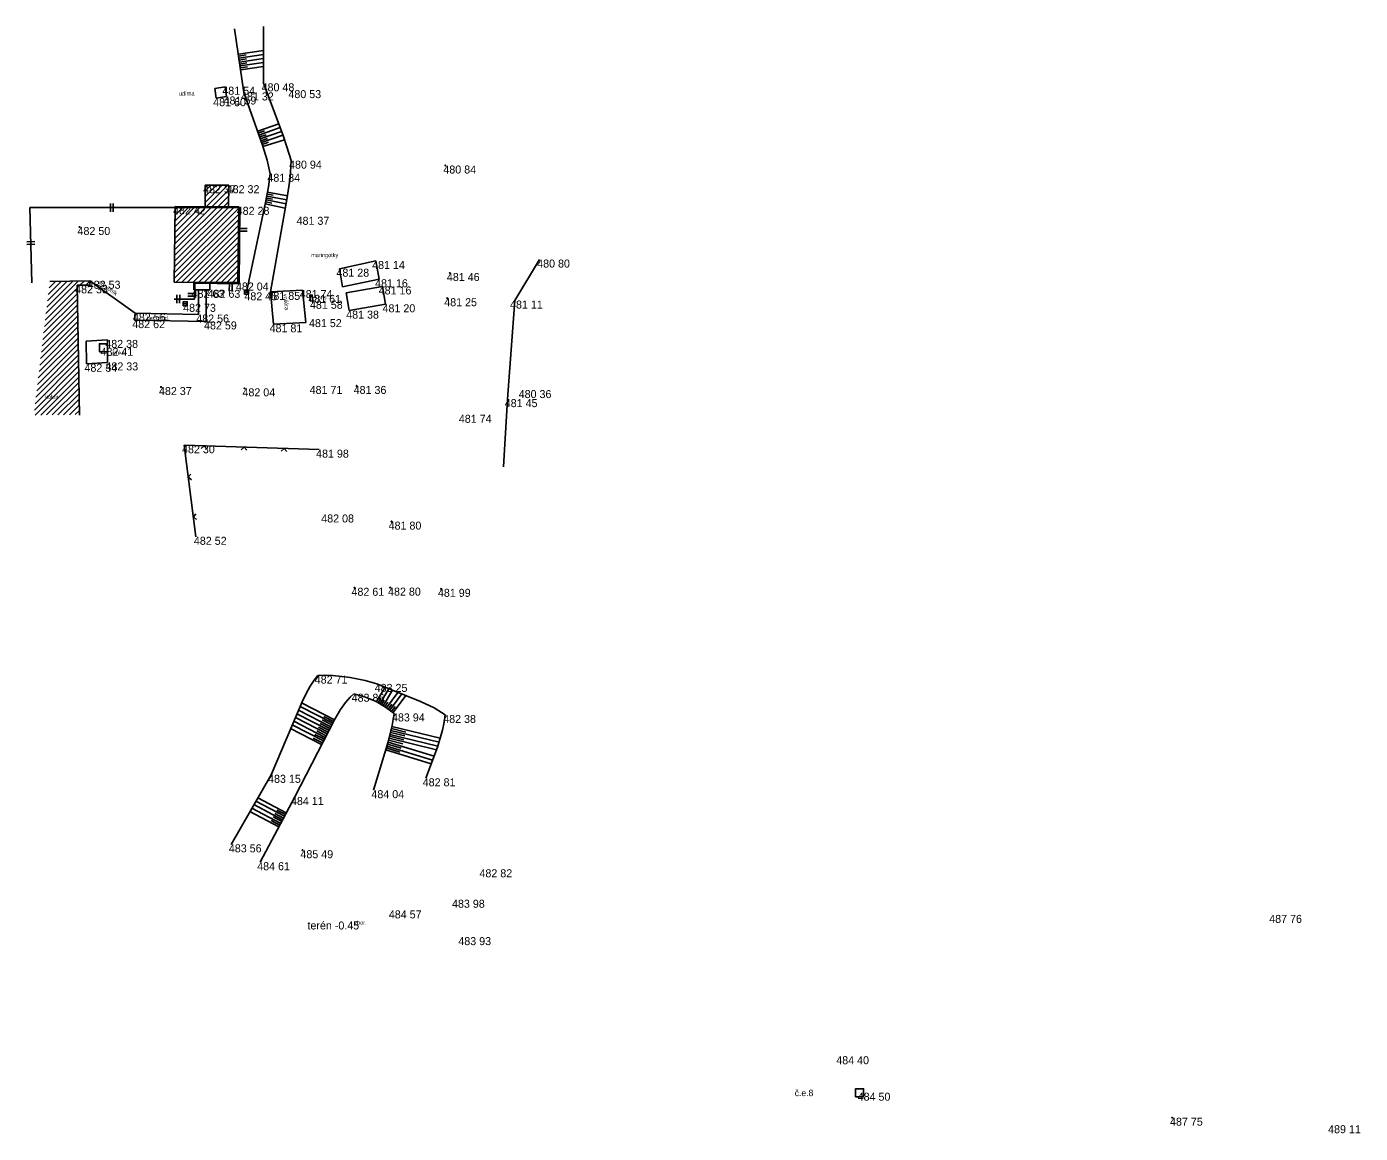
# Model space of a CAD drawing. Extents: x -553666 to -553461, y -1076543 to -1076230.
# Drawn here: x -553665.9 to -553499.2, y -1076368.4 to -1076230.1 of the extents above; entities that cross this region are included whole.
import ezdxf

# ---------------------------------------------------------------- set-up
doc = ezdxf.new("R2010")
doc.units = 0
for name, color, linetype in [('1', 7, 'Continuous'), ('12', 7, 'Continuous'), ('14', 7, 'Continuous'), ('17', 7, 'Continuous'), ('18', 7, 'Continuous'), ('26', 7, 'Continuous'), ('27', 7, 'Continuous'), ('32', 7, 'Continuous'), ('40', 7, 'Continuous'), ('50', 7, 'Continuous'), ('52', 7, 'Continuous'), ('54', 7, 'Continuous'), ('6', 7, 'Continuous'), ('62', 7, 'Continuous')]:
    doc.layers.add(name, color=color, linetype=linetype)

# ---------------------------------------------------------------- blocks, each defined once
blk = doc.blocks.new('POINT_DISPLAY')
blk.add_line((0, 0), (0, 0))
blk = doc.blocks.new('T')
at = {"layer": '6'}
blk.add_circle((0, 0), 0.05, dxfattribs=at)
blk = doc.blocks.new('VP')
at = {"layer": '40'}
blk.add_line((-0.25, 0), (0.25, 0), dxfattribs=at)
blk.add_lwpolyline([(-0.25, -0.25), (0.25, -0.25), (0.25, 0.25), (-0.25, 0.25)], close=True, dxfattribs=at)
blk = doc.blocks.new('SA')
at = {"layer": '50'}
blk.add_lwpolyline([(-0.5, -0.5), (0.5, -0.5), (0.5, 0.5), (-0.5, 0.5)], close=True, dxfattribs=at)
blk = doc.blocks.new('ROV')
at = {"layer": '62'}
for p, q in [((-0.348, -0.51), (-0.348, 0.51)), ((0, -0.51), (0, 0.51))]:
    blk.add_line(p, q, dxfattribs=at)

msp = doc.modelspace()

# ---------------------------------------------------------------- linework, layer by layer
at = {"layer": '12'}
for p, q in [((-553644.72, -1076293.84), (-553646.2, -1076282.4)), ((-553646.2, -1076282.4), (-553629.33, -1076282.95)), ((-553643.7, -1076282.48), (-553644.07, -1076282.82)), ((-553643.7, -1076282.48), (-553643.36, -1076282.85)), ((-553638.7, -1076282.64), (-553639.07, -1076282.99)), ((-553638.7, -1076282.64), (-553638.36, -1076283.01)), ((-553633.71, -1076282.81), (-553634.07, -1076283.15)), ((-553633.71, -1076282.81), (-553633.36, -1076283.17)), ((-553645.68, -1076286.4), (-553645.38, -1076286.01)), ((-553645.68, -1076286.4), (-553645.29, -1076286.71)), ((-553645.04, -1076291.36), (-553644.73, -1076290.96)), ((-553645.04, -1076291.36), (-553644.64, -1076291.67))]:
    msp.add_line(p, q, dxfattribs=at)
at = {"layer": '14'}
for p, q in [((-553641.07, -1076237.61), (-553642.37, -1076237.82)), ((-553642.37, -1076237.82), (-553642.19, -1076239.04)), ((-553641.07, -1076237.61), (-553640.89, -1076238.83)), ((-553640.89, -1076238.83), (-553642.19, -1076239.04)), ((-553643.59, -1076252.58), (-553643.57, -1076249.92)), ((-553640.62, -1076249.91), (-553643.57, -1076249.92)), ((-553640.64, -1076252.6), (-553640.62, -1076249.91)), ((-553647.33, -1076252.56), (-553647.44, -1076262.02)), ((-553647.33, -1076252.56), (-553639.37, -1076252.61)), ((-553639.37, -1076252.61), (-553639.48, -1076262.07)), ((-553662.98, -1076261.94), (-553657.98, -1076261.85)), ((-553657.97, -1076262.39), (-553659.56, -1076262.42)), ((-553659.56, -1076262.42), (-553659.27, -1076278.63)), ((-553657.97, -1076262.39), (-553657.98, -1076261.85)), ((-553647.44, -1076262.02), (-553639.48, -1076262.07))]:
    msp.add_line(p, q, dxfattribs=at)
at = {"layer": '17'}
for p, q in [((-553644.41, -1076262.98), (-553644.41, -1076266.07)), ((-553643.44, -1076262.98), (-553643.44, -1076266.93)), ((-553652.33, -1076265.91), (-553652.41, -1076266.77)), ((-553652.33, -1076265.91), (-553644.41, -1076266.07)), ((-553652.41, -1076266.77), (-553643.44, -1076266.93))]:
    msp.add_line(p, q, dxfattribs=at)
at = {"layer": '18'}
for p, q in [((-553626.8, -1076260.34), (-553622.24, -1076259.38)), ((-553622.24, -1076259.38), (-553621.85, -1076261.66)), ((-553626.8, -1076260.34), (-553626.41, -1076262.62)), ((-553652.33, -1076265.91), (-553657.98, -1076261.85)), ((-553644.99, -1076262.04), (-553645, -1076262.98)), ((-553645, -1076262.98), (-553643, -1076262.98)), ((-553642.99, -1076262.05), (-553643, -1076262.98)), ((-553635.42, -1076263.24), (-553631.39, -1076263.01)), ((-553631.39, -1076263.01), (-553631.01, -1076267.06)), ((-553626.41, -1076262.62), (-553621.85, -1076261.66)), ((-553621.4, -1076262.56), (-553625.94, -1076263.35)), ((-553621.4, -1076262.56), (-553621.04, -1076264.79)), ((-553635.42, -1076263.24), (-553635.04, -1076267.29)), ((-553630.49, -1076263.64), (-553630.19, -1076263.61)), ((-553630.49, -1076263.64), (-553630.41, -1076264.38)), ((-553630.11, -1076264.35), (-553630.41, -1076264.38)), ((-553630.19, -1076263.61), (-553630.11, -1076264.35)), ((-553625.94, -1076263.35), (-553625.58, -1076265.58)), ((-553621.04, -1076264.79), (-553625.58, -1076265.58)), ((-553635.04, -1076267.29), (-553631.01, -1076267.06)), ((-553655.79, -1076269.24), (-553658.42, -1076269.41)), ((-553658.42, -1076269.41), (-553658.4, -1076272.22)), ((-553655.79, -1076269.24), (-553655.77, -1076272.05)), ((-553655.77, -1076272.05), (-553658.4, -1076272.22))]:
    msp.add_line(p, q, dxfattribs=at)
at = {"layer": '26'}
for p, q in [((-553639.42, -1076233.53), (-553636.27, -1076233.07)), ((-553639.39, -1076233.78), (-553638.45, -1076233.64)), ((-553639.35, -1076234.02), (-553636.27, -1076233.57)), ((-553639.31, -1076234.27), (-553638.4, -1076234.14)), ((-553639.28, -1076234.52), (-553636.27, -1076234.08)), ((-553639.24, -1076234.77), (-553638.35, -1076234.64)), ((-553639.21, -1076235.01), (-553636.27, -1076234.58)), ((-553639.17, -1076235.26), (-553638.3, -1076235.13)), ((-553639.13, -1076235.51), (-553636.27, -1076235.09)), ((-553637.01, -1076243.17), (-553634.38, -1076242.25)), ((-553636.85, -1076243.65), (-553634.21, -1076242.72)), ((-553636.93, -1076243.41), (-553636.14, -1076243.13)), ((-553636.76, -1076243.88), (-553635.97, -1076243.6)), ((-553636.68, -1076244.12), (-553634.03, -1076243.19)), ((-553636.6, -1076244.35), (-553635.8, -1076244.07)), ((-553636.52, -1076244.59), (-553633.86, -1076243.66)), ((-553636.43, -1076244.82), (-553635.64, -1076244.54)), ((-553636.36, -1076245.06), (-553633.65, -1076244.24)), ((-553635.87, -1076251.26), (-553633.38, -1076251.75)), ((-553635.82, -1076251.02), (-553635.08, -1076251.16)), ((-553635.77, -1076250.77), (-553633.3, -1076251.25)), ((-553636.06, -1076252.24), (-553633.56, -1076252.78)), ((-553636.01, -1076252), (-553635.26, -1076252.14)), ((-553635.96, -1076251.75), (-553633.47, -1076252.24)), ((-553635.92, -1076251.51), (-553635.17, -1076251.65)), ((-553622.18, -1076314.44), (-553621.1, -1076312.63)), ((-553621.76, -1076314.7), (-553620.63, -1076312.82)), ((-553621.33, -1076314.95), (-553620.16, -1076313.01)), ((-553627.42, -1076316.69), (-553631.52, -1076314.58)), ((-553621.97, -1076314.57), (-553621.64, -1076314.01)), ((-553621.54, -1076314.82), (-553621.2, -1076314.25)), ((-553621.11, -1076315.08), (-553620.76, -1076314.49)), ((-553620.91, -1076315.22), (-553619.48, -1076313.28)), ((-553620.5, -1076315.52), (-553619, -1076313.47)), ((-553620.1, -1076315.81), (-553618.52, -1076313.66)), ((-553628.1, -1076318.02), (-553632.1, -1076315.96)), ((-553627.87, -1076317.57), (-553631.91, -1076315.5)), ((-553627.64, -1076317.13), (-553631.71, -1076315.04)), ((-553627.53, -1076316.91), (-553628.76, -1076316.28)), ((-553620.7, -1076315.37), (-553620.26, -1076314.77)), ((-553620.3, -1076315.67), (-553619.84, -1076315.04)), ((-553629.02, -1076319.8), (-553632.89, -1076317.81)), ((-553628.79, -1076319.35), (-553632.69, -1076317.35)), ((-553628.56, -1076318.91), (-553632.5, -1076316.89)), ((-553628.33, -1076318.47), (-553632.3, -1076316.43)), ((-553628.22, -1076318.24), (-553629.41, -1076317.63)), ((-553627.99, -1076317.8), (-553629.19, -1076317.18)), ((-553627.76, -1076317.35), (-553628.97, -1076316.73)), ((-553620.36, -1076318.04), (-553614.34, -1076319.5)), ((-553620.3, -1076317.8), (-553618.49, -1076318.24)), ((-553620.24, -1076317.56), (-553614.2, -1076319.02)), ((-553628.9, -1076319.58), (-553630.07, -1076318.98)), ((-553628.67, -1076319.13), (-553629.85, -1076318.53)), ((-553628.44, -1076318.69), (-553629.63, -1076318.08)), ((-553620.72, -1076319.5), (-553614.97, -1076321.26)), ((-553620.66, -1076319.26), (-553618.88, -1076319.69)), ((-553620.6, -1076319.01), (-553614.66, -1076320.45)), ((-553620.54, -1076318.77), (-553618.75, -1076319.2)), ((-553620.48, -1076318.53), (-553614.49, -1076319.98)), ((-553620.42, -1076318.28), (-553618.62, -1076318.72)), ((-553621.01, -1076320.45), (-553615.33, -1076322.2)), ((-553620.94, -1076320.22), (-553619.23, -1076320.74)), ((-553620.87, -1076319.98), (-553615.15, -1076321.73)), ((-553620.79, -1076319.74), (-553619.07, -1076320.27)), ((-553634.13, -1076329.65), (-553637.73, -1076327.74)), ((-553633.89, -1076329.21), (-553637.48, -1076327.3)), ((-553633.66, -1076328.76), (-553637.23, -1076326.87)), ((-553633.43, -1076328.32), (-553636.98, -1076326.44)), ((-553633.54, -1076328.54), (-553634.61, -1076327.98)), ((-553634.36, -1076330.09), (-553637.98, -1076328.17)), ((-553634.24, -1076329.87), (-553635.33, -1076329.29)), ((-553634.01, -1076329.43), (-553635.09, -1076328.85)), ((-553633.78, -1076328.99), (-553634.85, -1076328.42))]:
    msp.add_line(p, q, dxfattribs=at)
at = {"layer": '27'}
for p, q in [((-553638.72, -1076238.32), (-553639.89, -1076230.36)), ((-553636.28, -1076230.1), (-553636.27, -1076237.18)), ((-553601.82, -1076259.2), (-553604.89, -1076264.32)), ((-553604.89, -1076264.32), (-553605.78, -1076276.64)), ((-553605.78, -1076276.64), (-553606.31, -1076285.09)), ((-553640.34, -1076332.27), (-553635.34, -1076323.58)), ((-553636.7, -1076334.5), (-553632.38, -1076326.35))]:
    msp.add_line(p, q, dxfattribs=at)
for points in [[(-553636.27, -1076237.18), (-553633.84, -1076243.71), (-553633.35, -1076245.1), (-553632.83, -1076246.84)], [(-553638.72, -1076238.32), (-553636.41, -1076244.89), (-553635.84, -1076246.77), (-553635.44, -1076248.48)], [(-553632.83, -1076246.84), (-553632.96, -1076248.99), (-553633.37, -1076251.7), (-553635.42, -1076263.24)], [(-553635.44, -1076248.48), (-553635.65, -1076250.13), (-553636.03, -1076252.08), (-553638.42, -1076263.29)], [(-553635.34, -1076323.58), (-553631.46, -1076314.45), (-553630.97, -1076313.4), (-553630.46, -1076312.51), (-553629.97, -1076311.75), (-553629.51, -1076311.18)], [(-553629.51, -1076311.18), (-553628.6, -1076311.13), (-553627.66, -1076311.16), (-553626.51, -1076311.29), (-553625.45, -1076311.43), (-553623.56, -1076311.78), (-553622.13, -1076312.22)], [(-553622.13, -1076312.22), (-553616.68, -1076314.4), (-553614.98, -1076315.22), (-553613.57, -1076316.1)], [(-553632.38, -1076326.35), (-553627.39, -1076316.63), (-553626.67, -1076315.43), (-553626.04, -1076314.53), (-553625.47, -1076313.88), (-553625, -1076313.45)], [(-553625, -1076313.45), (-553623.52, -1076313.87), (-553622.21, -1076314.42), (-553621.03, -1076315.13), (-553619.97, -1076315.91)], [(-553619.97, -1076315.91), (-553620.21, -1076317.41), (-553620.7, -1076319.44), (-553622.56, -1076325.5)], [(-553613.57, -1076316.1), (-553613.69, -1076317.01), (-553613.91, -1076318.01), (-553614.53, -1076320.11), (-553616.02, -1076324.01)]]:
    msp.add_lwpolyline(points, dxfattribs=at)
at = {"layer": '32'}
for p, q in [((-553647.39, -1076257.27), (-553640.62, -1076250.51)), ((-553647.39, -1076257.99), (-553640.63, -1076251.22)), ((-553647.38, -1076256.56), (-553640.73, -1076249.91)), ((-553643.58, -1076252.06), (-553641.44, -1076249.91)), ((-553643.58, -1076250.63), (-553642.86, -1076249.92)), ((-553643.58, -1076251.34), (-553642.15, -1076249.92)), ((-553647.43, -1076260.85), (-553639.37, -1076252.79)), ((-553647.42, -1076260.13), (-553639.89, -1076252.61)), ((-553647.41, -1076259.42), (-553640.59, -1076252.6)), ((-553647.4, -1076258.7), (-553640.63, -1076251.93)), ((-553647.37, -1076255.84), (-553644.11, -1076252.58)), ((-553647.36, -1076255.12), (-553644.81, -1076252.58)), ((-553647.35, -1076254.41), (-553645.52, -1076252.57)), ((-553647.34, -1076252.98), (-553646.92, -1076252.56)), ((-553647.34, -1076253.69), (-553646.22, -1076252.57)), ((-553647.44, -1076261.56), (-553639.38, -1076253.51)), ((-553647.19, -1076262.02), (-553639.39, -1076254.22)), ((-553646.48, -1076262.03), (-553639.4, -1076254.94)), ((-553645.78, -1076262.03), (-553639.41, -1076255.66)), ((-553645.08, -1076262.04), (-553639.41, -1076256.37)), ((-553644.38, -1076262.04), (-553639.42, -1076257.09)), ((-553643.67, -1076262.04), (-553639.43, -1076257.8)), ((-553642.97, -1076262.05), (-553639.44, -1076258.52)), ((-553642.27, -1076262.05), (-553639.45, -1076259.23)), ((-553641.57, -1076262.06), (-553639.46, -1076259.95)), ((-553640.86, -1076262.06), (-553639.46, -1076260.66)), ((-553640.16, -1076262.07), (-553639.47, -1076261.38)), ((-553663.56, -1076266.76), (-553659.55, -1076262.76)), ((-553663.46, -1076265.96), (-553659.38, -1076261.88)), ((-553663.36, -1076265.16), (-553660.1, -1076261.89)), ((-553663.27, -1076264.35), (-553660.82, -1076261.9)), ((-553663.17, -1076263.55), (-553661.54, -1076261.92)), ((-553663.08, -1076262.75), (-553662.26, -1076261.93)), ((-553659.21, -1076262.41), (-553658.66, -1076261.86)), ((-553658.48, -1076262.4), (-553657.98, -1076261.89)), ((-553663.75, -1076268.37), (-553659.53, -1076264.15)), ((-553663.65, -1076267.57), (-553659.54, -1076263.45)), ((-553664.04, -1076270.78), (-553659.49, -1076266.23)), ((-553663.94, -1076269.98), (-553659.5, -1076265.54)), ((-553663.85, -1076269.17), (-553659.51, -1076264.84)), ((-553664.23, -1076272.39), (-553659.47, -1076267.62)), ((-553664.13, -1076271.58), (-553659.48, -1076266.93)), ((-553664.52, -1076274.8), (-553659.43, -1076269.71)), ((-553664.42, -1076273.99), (-553659.44, -1076269.01)), ((-553664.33, -1076273.19), (-553659.45, -1076268.32)), ((-553664.71, -1076276.4), (-553659.41, -1076271.1)), ((-553664.62, -1076275.6), (-553659.42, -1076270.4)), ((-553664.91, -1076278.01), (-553659.38, -1076272.49)), ((-553664.81, -1076277.21), (-553659.39, -1076271.79)), ((-553664.83, -1076278.64), (-553659.37, -1076273.18)), ((-553664.11, -1076278.63), (-553659.35, -1076273.88)), ((-553663.39, -1076278.62), (-553659.34, -1076274.57)), ((-553662.68, -1076278.61), (-553659.33, -1076275.26)), ((-553661.96, -1076278.6), (-553659.32, -1076275.96)), ((-553661.25, -1076278.59), (-553659.31, -1076276.65)), ((-553660.53, -1076278.59), (-553659.29, -1076277.35)), ((-553659.81, -1076278.58), (-553659.28, -1076278.04))]:
    msp.add_line(p, q, dxfattribs=at)
at = {"layer": '62'}
for p, q in [((-553639.24, -1076252.71), (-553665.47, -1076252.71)), ((-553665.47, -1076252.71), (-553665.23, -1076262.09)), ((-553639.24, -1076252.71), (-553639.33, -1076262.22)), ((-553644.87, -1076262.17), (-553644.89, -1076264.16)), ((-553639.33, -1076262.22), (-553644.87, -1076262.17)), ((-553644.89, -1076264.16), (-553647.43, -1076264.14))]:
    msp.add_line(p, q, dxfattribs=at)

# ---------------------------------------------------------------- block references
at = {"layer": '1'}
for p in [(-553641.07, -1076237.61), (-553636.27, -1076237.18), (-553632.91, -1076238.03), (-553642.19, -1076239.04), (-553640.89, -1076238.83), (-553638.72, -1076238.32), (-553632.83, -1076246.84), (-553613.56, -1076247.45), (-553635.44, -1076248.48), (-553643.57, -1076249.92), (-553640.62, -1076249.91), (-553647.33, -1076252.56), (-553639.37, -1076252.61), (-553631.78, -1076253.86), (-553659.26, -1076255.13), (-553622.24, -1076259.38), (-553601.82, -1076259.2), (-553626.8, -1076260.34), (-553613, -1076260.88), (-553659.56, -1076262.42), (-553657.98, -1076261.85), (-553645, -1076262.98), (-553643, -1076262.98), (-553639.48, -1076262.07), (-553631.39, -1076263.01), (-553621.85, -1076261.66), (-553621.4, -1076262.56), (-553638.42, -1076263.29), (-553635.42, -1076263.24), (-553630.19, -1076263.61), (-553630.11, -1076264.35), (-553613.33, -1076264.03), (-553604.89, -1076264.32), (-553652.33, -1076265.91), (-553646.06, -1076264.73), (-553644.41, -1076266.07), (-553625.58, -1076265.58), (-553621.04, -1076264.79), (-553652.41, -1076266.77), (-553643.44, -1076266.93), (-553635.04, -1076267.29), (-553630.23, -1076266.64), (-553655.79, -1076269.24), (-553656.28, -1076270.23), (-553658.4, -1076272.22), (-553655.77, -1076272.05), (-553649.08, -1076275.13), (-553638.66, -1076275.29), (-553630.04, -1076274.99), (-553624.64, -1076274.99), (-553604.12, -1076275.51), (-553605.78, -1076276.64), (-553611.52, -1076278.6), (-553646.2, -1076282.4), (-553629.33, -1076282.95), (-553628.81, -1076291.05), (-553620.28, -1076291.94), (-553644.72, -1076293.84), (-553624.91, -1076300.21), (-553620.46, -1076300.19), (-553614.1, -1076300.34), (-553629.51, -1076311.18), (-553622.13, -1076312.22), (-553625, -1076313.45), (-553619.97, -1076315.91), (-553613.57, -1076316.1), (-553635.34, -1076323.58), (-553616.02, -1076324.01), (-553632.38, -1076326.35), (-553622.56, -1076325.5), (-553640.34, -1076332.27), (-553631.41, -1076333), (-553636.7, -1076334.5), (-553609.04, -1076335.38), (-553612.46, -1076339.19), (-553620.37, -1076340.52), (-553510.36, -1076341.08), (-553611.67, -1076343.86), (-553564.48, -1076358.74), (-553561.8, -1076363.3), (-553522.76, -1076366.42), (-553502.78, -1076367.36)]:
    msp.add_blockref('POINT_DISPLAY', p, dxfattribs=at)
at = {"layer": '18'}
msp.add_blockref('POINT_DISPLAY', (-553600.55, -1076259.73), dxfattribs=at)
at = {"layer": '32'}
for p in [(-553643.57, -1076249.92), (-553662.98, -1076261.94)]:
    msp.add_blockref('POINT_DISPLAY', p, dxfattribs=at)
at = {"layer": '40'}
for p in [(-553638.42, -1076263.29), (-553646.06, -1076264.73)]:
    msp.add_blockref('VP', p, dxfattribs=at)
at = {"layer": '50'}
for p in [(-553656.28, -1076270.23), (-553561.8, -1076363.3)]:
    msp.add_blockref('SA', p, dxfattribs=at)
at = {"layer": '6'}
for p in [(-553613.56, -1076247.45), (-553659.26, -1076255.13), (-553613, -1076260.88), (-553613.33, -1076264.03), (-553649.08, -1076275.13), (-553638.66, -1076275.29), (-553624.64, -1076274.99), (-553620.28, -1076291.94), (-553624.91, -1076300.21), (-553620.46, -1076300.19), (-553614.1, -1076300.34), (-553631.41, -1076333), (-553522.76, -1076366.42)]:
    msp.add_blockref('T', p, dxfattribs=at)
at = {"layer": '62'}
msp.add_blockref('ROV', (-553655.05, -1076252.71), dxfattribs=at)
for p, xscale, yscale, rotation in [((-553638.83, -1076255.66), 0.9999982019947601, 0.99999820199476, -90.54215625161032), ((-553665.35, -1076257.31), 0.9999982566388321, 0.9999982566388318, -88.54095157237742), ((-553640.55, -1076262.66), 1.0000021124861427, 1.0000021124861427, 179.4623817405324), ((-553646.76, -1076264.13), 0.999998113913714, 0.9999981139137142, -0.5416226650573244), ((-553645.21, -1076263.43), 0.999998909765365, 0.999998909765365, 89.45357505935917)]:
    msp.add_blockref('ROV', p, dxfattribs=dict(at, xscale=xscale, yscale=yscale, rotation=rotation))

# ---------------------------------------------------------------- texts
at = {"layer": '52'}
for s, p in [('udírna', (-553646.86, -1076238.71)), ('maringotky', (-553630.32, -1076258.9)), ('pris', (-553629.52, -1076264.18)), ('bet.chod.', (-553650.89, -1076266.75)), ('jímka', (-553655.26, -1076271.08)), ('kolna', (-553663.55, -1076276.61)), ('zbor.', (-553624.93, -1076342.31))]:
    msp.add_text(s, height=0.5, dxfattribs=at).set_placement(p)
for s, rotation, p in [('obrubník', 324.2996, (-553656.95, -1076262.14)), ('voliéra', 275.3602, (-553633.8, -1076263.51))]:
    msp.add_text(s, height=0.5, rotation=rotation, dxfattribs=at).set_placement(p)
at = {"layer": '54'}
msp.add_text('č.e.8', height=0.8, dxfattribs=at).set_placement((-553569.91, -1076363.73))
at = {"layer": '6'}
for s, p in [('481 54 ', (-553641.43, -1076238.61)), ('480 48 ', (-553636.52, -1076238.18)), ('480 53 ', (-553633.17, -1076239.03)), ('481 60 ', (-553642.57, -1076240.04)), ('481 59 ', (-553641.27, -1076239.83)), ('481 32 ', (-553639.09, -1076239.32)), ('480 94 ', (-553633.09, -1076247.84)), ('480 84 ', (-553613.81, -1076248.45)), ('481 84 ', (-553635.8, -1076249.48)), ('482 37 ', (-553643.83, -1076250.92)), ('482 32 ', (-553640.88, -1076250.91)), ('482 42 ', (-553647.58, -1076253.56)), ('482 28 ', (-553639.63, -1076253.61)), ('481 37 ', (-553632.15, -1076254.86)), ('482 50 ', (-553659.52, -1076256.13)), ('481 14 ', (-553622.71, -1076260.38)), ('480 80 ', (-553602.09, -1076260.2)), ('481 28 ', (-553627.17, -1076261.34)), ('481 46 ', (-553613.37, -1076261.88)), ('482 33 ', (-553659.82, -1076263.42)), ('482 53 ', (-553658.24, -1076262.85)), ('482 63 ', (-553645.27, -1076263.98)), ('482 63 ', (-553643.27, -1076263.98)), ('482 04 ', (-553639.73, -1076263.07)), ('481 74 ', (-553631.75, -1076264.01)), ('481 16 ', (-553622.34, -1076262.66)), ('481 16 ', (-553621.89, -1076263.56)), ('482 73 ', (-553646.32, -1076265.73)), ('482 45 ', (-553638.67, -1076264.29)), ('481 85 ', (-553635.79, -1076264.24)), ('481 61 ', (-553630.68, -1076264.61)), ('481 58 ', (-553630.48, -1076265.35)), ('481 25 ', (-553613.7, -1076265.03)), ('481 11 ', (-553605.48, -1076265.32)), ('482 56 ', (-553652.6, -1076266.91)), ('482 56 ', (-553644.68, -1076267.07)), ('481 38 ', (-553625.95, -1076266.58)), ('481 20 ', (-553621.41, -1076265.79)), ('482 62 ', (-553652.68, -1076267.77)), ('482 59 ', (-553643.71, -1076267.93)), ('481 81 ', (-553635.52, -1076268.29)), ('481 52 ', (-553630.6, -1076267.64)), ('482 38 ', (-553656.05, -1076270.24)), ('482 41 ', (-553656.64, -1076271.23)), ('482 34 ', (-553658.65, -1076273.22)), ('482 33 ', (-553656.03, -1076273.05)), ('482 37 ', (-553649.34, -1076276.13)), ('482 04 ', (-553638.91, -1076276.29)), ('481 71 ', (-553630.52, -1076275.99)), ('481 36 ', (-553625.02, -1076275.99)), ('480 36 ', (-553604.4, -1076276.51)), ('481 45 ', (-553606.14, -1076277.64)), ('481 74 ', (-553611.88, -1076279.6)), ('482 30 ', (-553646.46, -1076283.4)), ('481 98 ', (-553629.71, -1076283.95)), ('482 08 ', (-553629.07, -1076292.05)), ('481 80 ', (-553620.65, -1076292.94)), ('482 52 ', (-553644.98, -1076294.84)), ('482 61 ', (-553625.29, -1076301.21)), ('482 80 ', (-553620.72, -1076301.19)), ('481 99 ', (-553614.49, -1076301.34)), ('482 71 ', (-553629.88, -1076312.18)), ('483 25 ', (-553622.39, -1076313.22)), ('483 86 ', (-553625.27, -1076314.45)), ('483 94 ', (-553620.23, -1076316.91)), ('482 38 ', (-553613.83, -1076317.1)), ('483 15 ', (-553635.71, -1076324.58)), ('482 81 ', (-553616.39, -1076325.01)), ('484 11 ', (-553632.85, -1076327.35)), ('484 04 ', (-553622.8, -1076326.5)), ('483 56 ', (-553640.61, -1076333.27)), ('485 49 ', (-553631.67, -1076334)), ('484 61 ', (-553637.07, -1076335.5)), ('482 82 ', (-553609.3, -1076336.38)), ('483 98 ', (-553612.73, -1076340.19)), ('484 57 ', (-553620.62, -1076341.52)), ('487 76 ', (-553510.63, -1076342.08)), ('terén -0.45', (-553630.79, -1076342.9)), ('483 93 ', (-553611.94, -1076344.86)), ('484 40 ', (-553564.72, -1076359.74)), ('484 50 ', (-553562.05, -1076364.3)), ('487 75 ', (-553523.02, -1076367.42)), ('489 11 ', (-553503.27, -1076368.36))]:
    msp.add_text(s, height=1, dxfattribs=at).set_placement(p)

doc.saveas('drawing.dxf')
